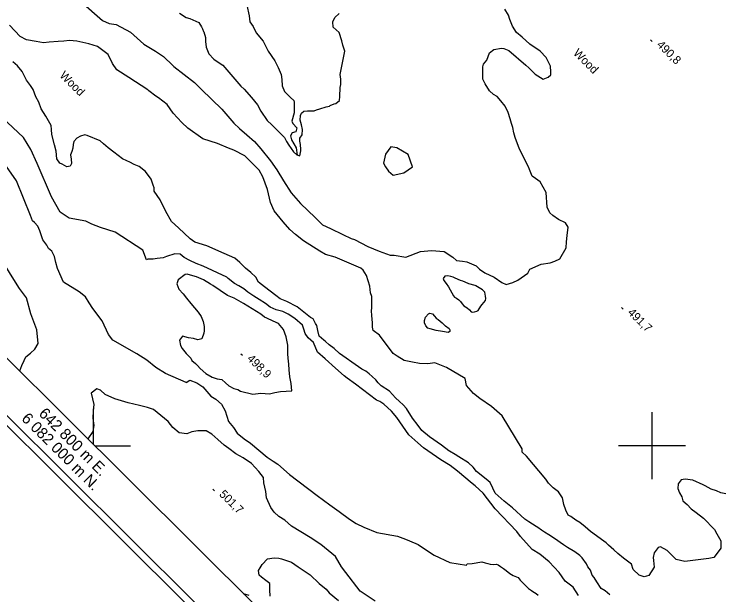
# Model space of a CAD drawing. Extents: x 642515 to 647219, y 6080136 to 6084356.
# Drawn here: x 642771.6 to 643026.5, y 6081946.7 to 6082154.5 of the extents above; entities that cross this region are included whole.
import ezdxf

# ---------------------------------------------------------------- set-up
doc = ezdxf.new("R2010")
doc.units = 0
for name, color, linetype in [('Level 1', 7, 'Continuous'), ('Level 2', 7, 'Continuous'), ('Level 3', 7, 'Continuous'), ('Level 4', 7, 'Continuous'), ('Level 44', 7, 'Continuous'), ('Level 60', 7, 'Continuous'), ('Level 61', 7, 'Continuous')]:
    doc.layers.add(name, color=color, linetype=linetype)

msp = doc.modelspace()

# ---------------------------------------------------------------- linework, layer by layer
at = {"layer": 'Level 1'}
for points in [[(642795.5, 6082159.13), (642803.18, 6082152.26), (642805.67, 6082151.27), (642808.12, 6082150.92), (642813.3, 6082148.12), (642818.08, 6082143.85), (642822.28, 6082141.33), (642825.14, 6082139.38), (642828.41, 6082136.15), (642828.41, 6082136.15), (642828.75, 6082135.85), (642836.19, 6082130.16), (642838.6, 6082127.72), (642842.37, 6082124.07), (642845.97, 6082120.58), (642850.32, 6082115.51), (642852.36, 6082113.7), (642854.92, 6082111.43), (642857.65, 6082109.01), (642859.91, 6082106.4), (642863.4, 6082102.09), (642865.69, 6082098.84), (642868.03, 6082094.94), (642870.87, 6082090.59), (642874.17, 6082086.75), (642879.48, 6082081.74), (642882.06, 6082079.16), (642884.88, 6082077.87), (642889.36, 6082075.72), (642892.36, 6082074.28), (642893.51, 6082073.87), (642898.34, 6082071.41), (642902.31, 6082069.71), (642906.27, 6082068.34), (642907.72, 6082068.26), (642911.96, 6082067.55), (642917.15, 6082069.63), (642921.16, 6082070.03), (642925.7, 6082069.66), (642928.73, 6082067.58), (642930.09, 6082066.37), (642932.2, 6082066.17), (642933.75, 6082065.86), (642937.06, 6082064.45), (642938.34, 6082063.31), (642940.19, 6082061.97), (642943.52, 6082060.39), (642946.37, 6082058.47), (642947.87, 6082057.75), (642950.24, 6082058.54), (642952.04, 6082059.37)], [(642961.08, 6082131.3), (642962.9, 6082131.97), (642963.81, 6082132.83), (642963.83, 6082133.88), (642963.7, 6082135.97), (642962.22, 6082139.11), (642960.07, 6082141.32), (642956.36, 6082143.84), (642953.55, 6082146.33), (642951.59, 6082148.07), (642950.17, 6082150.25), (642949.22, 6082152.61), (642948.71, 6082154.27), (642947.38, 6082156.37)], [(642952.04, 6082059.37), (642955.6, 6082061.84), (642956.31, 6082063.34), (642960.4, 6082065.03), (642963.59, 6082065.55), (642965.33, 6082066.13), (642967.05, 6082067.04), (642969.39, 6082070.89), (642969.5, 6082073.08), (642969.68, 6082075.35), (642970.06, 6082078.36), (642969.08, 6082079.83), (642966.67, 6082081.06), (642964.57, 6082082.46), (642963.46, 6082083.45), (642962.53, 6082085.49), (642962.2, 6082090.79), (642960.04, 6082094.54), (642958.35, 6082095.73), (642957.17, 6082096.62), (642956.22, 6082098.99), (642955.84, 6082099.93), (642952.63, 6082106.27), (642951.09, 6082110.38), (642950.66, 6082112.13), (642950.3, 6082113.96), (642949.81, 6082115.46), (642949.3, 6082117.13), (642948.6, 6082119.42), (642947.49, 6082121.62), (642946.01, 6082123.54), (642944.62, 6082125.08), (642943.29, 6082125.8), (642941.84, 6082127.09), (642940.31, 6082129.66), (642939.49, 6082131.3), (642939.49, 6082132.51), (642939.46, 6082134.37), (642939.45, 6082135.74), (642939.72, 6082136.72), (642940.92, 6082138.08), (642941.89, 6082140.72), (642943.43, 6082141.94), (642946.14, 6082142.42), (642947.03, 6082142.24), (642948.85, 6082141.54), (642954.89, 6082136.33), (642956, 6082135.35), (642958.31, 6082133.15), (642961.08, 6082131.3)], [(642914.29, 6082099.91), (642912.73, 6082104.34), (642908.71, 6082106.68), (642906.59, 6082107.04), (642904.65, 6082104.5), (642903.89, 6082101.23), (642904.61, 6082099.98), (642905.67, 6082098.43), (642907.38, 6082096.92), (642911.19, 6082097.79), (642914.29, 6082099.91)], [(642780.2, 6082036.7), (642779.73, 6082041.54), (642777.62, 6082047.34), (642775.99, 6082053.01), (642773.54, 6082056.39), (642770.89, 6082060.55), (642766.29, 6082067.65), (642766.29, 6082067.65), (642766.29, 6082067.65), (642766.56, 6082068.63), (642765.23, 6082075.14), (642765.02, 6082078.99), (642766.31, 6082081.79), (642766.86, 6082086.48), (642766.85, 6082089.54), (642766.44, 6082091.12), (642765.45, 6082094.44), (642763.59, 6082096.11), (642761.43, 6082097.43), (642759.58, 6082098.78), (642753, 6082104.36)], [(642773.6, 6082026.78), (642773.67, 6082026.94), (642774.28, 6082028.82), (642775.21, 6082030.56), (642775.77, 6082031.87), (642777.45, 6082033.26), (642779.04, 6082034.71), (642780.2, 6082036.7)], [(642900.93, 6081944.47), (642895.6, 6081948), (642890.38, 6081954.73), (642888.82, 6081956.72), (642886.67, 6081960.43), (642881.45, 6081964.76), (642877.61, 6081967.26), (642874.29, 6081969.3), (642870.96, 6081971.34), (642868.59, 6081973.44), (642866.43, 6081974.76), (642864.74, 6081976.26), (642863.52, 6081977.94), (642862.03, 6081981.38), (642861.72, 6081983.76), (642861.06, 6081986.77), (642860.94, 6081988.68), (642859.21, 6081990.82), (642856.63, 6081993.71), (642853.62, 6081995.77), (642850.97, 6081997.21), (642848.45, 6081999.14), (642846.78, 6082000.33), (642844.58, 6082002.28), (642842.38, 6082004.23), (642840.39, 6082005.39), (642837.35, 6082005.37), (642835.29, 6082005.08), (642833.41, 6082004.33), (642830.67, 6082004.65), (642828.47, 6082006.6), (642826.74, 6082008.73), (642821.51, 6082013.07), (642819.39, 6082013.74), (642816.46, 6082014.53), (642812.4, 6082015.4), (642807.67, 6082016.88), (642804.21, 6082018.44), (642802.52, 6082019.94), (642801.21, 6082020.5), (642799.22, 6082018.94), (642800.11, 6082014.83), (642799.93, 6082012.58), (642799.77, 6082010), (642800.09, 6082007.3), (642799.74, 6082005.2), (642797.99, 6082002.54)]]:
    msp.add_lwpolyline(points, dxfattribs=at)
at = {"layer": 'Level 2'}
for points in [[(642830.77, 6082154.98), (642833.22, 6082153.41), (642834.54, 6082153), (642837.71, 6082151.55), (642838.68, 6082150.06), (642839.05, 6082149.27), (642839.43, 6082148.32), (642839.43, 6082148.32), (642839.52, 6082148.24), (642840.13, 6082146.18), (642840.13, 6082144.8), (642840.33, 6082142.79), (642841.37, 6082140.35), (642843.1, 6082138.51), (642845.05, 6082137.1), (642846.31, 6082136.28), (642852.82, 6082128.83), (642854.02, 6082127.77), (642856.63, 6082124.69), (642858.73, 6082122.07), (642859.99, 6082119.88), (642862.22, 6082116.54), (642863.85, 6082114.94), (642866.59, 6082112.36), (642868.4, 6082110.44), (642869.14, 6082109.03), (642870.03, 6082107.63), (642870.83, 6082106.47), (642871.63, 6082105.3), (642872.91, 6082104.17), (642873.89, 6082103.9), (642874.35, 6082105.63), (642874.24, 6082106.18), (642874.22, 6082107.88), (642873.9, 6082109.07), (642873.99, 6082110.21), (642874.73, 6082111.39), (642874.93, 6082113.34), (642874.51, 6082114.93), (642874, 6082116.6)], [(642874, 6082116.6), (642874.14, 6082118.3), (642874.58, 6082119.13), (642875.42, 6082119.91), (642876.7, 6082119.99), (642878.08, 6082119.99), (642879.13, 6082119.97), (642879.91, 6082120.34), (642881.11, 6082120.65), (642883.4, 6082121.36), (642884.6, 6082121.67), (642884.82, 6082121.93), (642886.24, 6082122.5), (642886.8, 6082122.61), (642888.19, 6082123.66), (642888.26, 6082125.12), (642888.39, 6082128.36), (642888.65, 6082129.34), (642888.61, 6082131.36), (642888.35, 6082132.96), (642890.01, 6082141.38), (642889.4, 6082143.45), (642888.98, 6082145.04), (642888.07, 6082147.97), (642885.94, 6082149.87), (642885.73, 6082151.88), (642886.45, 6082153.37), (642887.98, 6082154.76)], [(642899.76, 6082053.52), (642899.2, 6082054.78), (642898.96, 6082057.26), (642897.85, 6082060.98), (642896.68, 6082062.93), (642895.83, 6082063.68), (642886.57, 6082067.64), (642883.13, 6082068.56), (642881.13, 6082069.73), (642875.27, 6082073.41), (642872.39, 6082075.66), (642870.35, 6082077.47), (642867.93, 6082080.22), (642864.78, 6082084.22), (642863.47, 6082087.21), (642862.39, 6082091.82), (642860.66, 6082096.39), (642859.39, 6082098.73), (642854.24, 6082103.9), (642850.25, 6082105.92), (642848.44, 6082106.61), (642844.47, 6082108.31), (642839.22, 6082109.93), (642833.82, 6082113.8), (642831.61, 6082115.76), (642828.51, 6082119.12), (642826.38, 6082122.22), (642823.34, 6082124.62), (642822.34, 6082125.2), (642819.8, 6082127.14), (642819.8, 6082127.14), (642819.46, 6082127.45), (642812.73, 6082131.93), (642808.37, 6082134.6), (642806.79, 6082136.94), (642805.32, 6082140.1), (642801.43, 6082142.96), (642798.3, 6082143.92), (642794.03, 6082144.97), (642791.43, 6082145.15), (642789.34, 6082144.88), (642787.4, 6082144.77), (642784.17, 6082144.59), (642782.08, 6082144.32), (642779.46, 6082144.82), (642776.03, 6082145.44), (642773.7, 6082146.6), (642769.91, 6082150.6)], [(642786.65, 6082105.55), (642786.02, 6082107.76), (642785.05, 6082111.48), (642784.93, 6082113.24), (642784.84, 6082114.68), (642782.93, 6082118.02), (642781.22, 6082120.73), (642780.42, 6082123.09), (642779.4, 6082125.03), (642778.43, 6082127.55), (642777.45, 6082129.01), (642775.95, 6082130.92), (642775.29, 6082132.41), (642774.46, 6082134.05), (642772.79, 6082136.11), (642771.17, 6082137.53)], [(642821.45, 6082066.84), (642819.52, 6082066.89), (642818.97, 6082066.61), (642817.64, 6082070.07), (642807.77, 6082076.55), (642802.53, 6082078.16), (642799.4, 6082079.42), (642797.25, 6082080.42), (642791.24, 6082081.51), (642788.06, 6082083.73), (642785, 6082089.17), (642785, 6082089.17), (642779.81, 6082101.14), (642777.6, 6082106.18), (642774.94, 6082110.38), (642767.28, 6082117.54)], [(642880.91, 6082039.34), (642880.38, 6082041.32), (642880.01, 6082043.14), (642879.57, 6082043.84), (642878.73, 6082045.47), (642877.73, 6082046.05), (642872.98, 6082049.77), (642869.23, 6082051.69), (642866.91, 6082052.67), (642865.39, 6082053.86), (642861.32, 6082056.97), (642859.19, 6082058.69), (642858.19, 6082060.47), (642856.4, 6082062.04), (642854.44, 6082063.61), (642852.46, 6082065.65), (642850.66, 6082067.22), (642846.85, 6082068.91), (642840.64, 6082071.64), (642836.36, 6082072.97), (642834.68, 6082074.15), (642830.47, 6082078.14), (642827.91, 6082080.39), (642825.9, 6082083.96), (642823.85, 6082088.17), (642821.8, 6082091.18), (642821.8, 6082092.38), (642821.41, 6082093.32), (642820.62, 6082095.52), (642818.6, 6082098.21), (642816.39, 6082100), (642814.64, 6082100.77), (642813.06, 6082101.55), (642811.99, 6082102.04), (642810.41, 6082102.83), (642807.28, 6082105.12), (642805.24, 6082106.76), (642803.61, 6082108.18), (642802.42, 6082109.23), (642797.78, 6082111.18), (642796.89, 6082111.36), (642795.3, 6082110.94), (642793.99, 6082110.13), (642793.02, 6082109.02), (642792.77, 6082107.88), (642792.61, 6082106.66), (642792.29, 6082105.43), (642791.73, 6082104.27), (642791.99, 6082102.68), (642792.1, 6082101.07), (642791.6, 6082100.15), (642790.49, 6082099.92), (642788.73, 6082100.85), (642787.9, 6082101.28), (642786.83, 6082102.82), (642786.65, 6082105.55)], [(642787.17, 6082063.57), (642786.56, 6082065.62), (642786.1, 6082067.84), (642785.03, 6082069.7), (642783.84, 6082070.75), (642783.29, 6082071.84), (642781.81, 6082073.76), (642780.81, 6082077.07), (642780.07, 6082078.63), (642778.87, 6082080), (642778.19, 6082080.6), (642777.44, 6082082.49), (642772.4, 6082094.93), (642765.41, 6082104.84)], [(642939.59, 6081983.15), (642936.7, 6081985.7), (642935.68, 6081986.61), (642930.44, 6081990.95), (642927.75, 6081993.04), (642924.41, 6081995.09), (642918.21, 6081999.37), (642916.17, 6082001.18), (642912.95, 6082004.04), (642910.83, 6082007.13), (642908.72, 6082010.21), (642906.81, 6082012.51), (642904.09, 6082014.91), (642902.59, 6082015.95), (642901.44, 6082016.36), (642893.86, 6082022.17), (642890.84, 6082024.24), (642889.82, 6082025.14), (642886.77, 6082027.85), (642883.03, 6082031.16), (642880.32, 6082033.57), (642878.82, 6082037.02), (642876.96, 6082038.67), (642875.9, 6082040.22), (642875.4, 6082041.87), (642874.91, 6082043.21), (642872.11, 6082045.69), (642869.78, 6082047.16), (642867.79, 6082048.16), (642865.42, 6082048.75), (642863.28, 6082049.74), (642861.67, 6082051.01), (642859.42, 6082052.4), (642857.5, 6082053.65), (642855.25, 6082055.04), (642853.89, 6082056.25), (642852.13, 6082057.35), (642850.56, 6082058.14), (642848.28, 6082060.01), (642847.77, 6082060.46), (642839.26, 6082064.37), (642836.79, 6082065.35), (642834.56, 6082066.42), (642832.49, 6082067.5), (642831.05, 6082068.62), (642829.12, 6082068.83), (642826.21, 6082067.77), (642824.95, 6082067.37), (642822.79, 6082067.16), (642821.45, 6082066.84)], [(642833.27, 6082022.7), (642825.86, 6082025.94), (642822.36, 6082028.14), (642819.16, 6082030.67), (642815.49, 6082033.02), (642806.93, 6082037.88), (642805.37, 6082039.88), (642803.06, 6082044.79), (642799.75, 6082049.24), (642798.5, 6082051.26), (642797.17, 6082053.34), (642794.89, 6082055.21), (642789.31, 6082058.65), (642787.17, 6082063.57)], [(642938.81, 6082050.02), (642939.25, 6082050.69), (642940.46, 6082052.05), (642940.53, 6082052.82), (642940.52, 6082053.66), (642940.19, 6082055.01), (642939.33, 6082055.93), (642938.16, 6082056.58), (642937.04, 6082057.28), (642936.7, 6082057.42), (642934.49, 6082058.09), (642933.13, 6082058.62), (642932.3, 6082058.97), (642931.56, 6082059.25), (642930.69, 6082059.64), (642929.37, 6082060.21), (642928.92, 6082060.38), (642928.02, 6082060.65), (642927, 6082060.87), (642925.95, 6082060.81), (642925.28, 6082059.96), (642925.53, 6082059.21), (642926.31, 6082058.21), (642927.23, 6082057.02), (642929, 6082053.78), (642929.39, 6082053.28), (642930.1, 6082052.96), (642930.86, 6082052.28), (642931.5, 6082051.71), (642932.07, 6082050.9), (642932.72, 6082050.17), (642933.31, 6082049.81), (642933.89, 6082049.44), (642934.7, 6082048.72), (642935.27, 6082048.07), (642935.84, 6082047.86), (642936.48, 6082047.98), (642937.31, 6082048.23), (642937.89, 6082048.55), (642938.81, 6082050.02)], [(643000.55, 6081960.06), (643000.69, 6081959.02), (643000.84, 6081956.61), (642999.01, 6081953.68), (642997.35, 6081953.18), (642995.46, 6081953.79), (642993.41, 6081955.76), (642992.81, 6081957.66), (642989.86, 6081959.82), (642987.9, 6081961.55), (642986.46, 6081962.83), (642984.58, 6081964.5), (642983.65, 6081965.33), (642982.81, 6081965.92), (642978.09, 6081969.34), (642976.13, 6081971.08), (642974.27, 6081972.58), (642972.77, 6081973.45), (642971.07, 6081974.8), (642970.08, 6081975.23), (642969.25, 6081977.03), (642968.48, 6081979.08), (642968.09, 6081981.39), (642966.59, 6081983.64), (642964.65, 6081985.05), (642963.02, 6081986.65), (642962.05, 6081988.12), (642955.1, 6081996.41), (642953.57, 6081997.76), (642953.57, 6081998.97), (642946.41, 6082010.79), (642942.58, 6082014.19), (642938.38, 6082017), (642936.18, 6082018.8), (642933.67, 6082021.63), (642933.12, 6082024.1), (642926.43, 6082028.05), (642922.31, 6082029.73), (642919.75, 6082029.42), (642916.84, 6082029.57), (642914.32, 6082029.98), (642911.38, 6082030.61), (642908.79, 6082032.15), (642907.37, 6082033.11), (642902.54, 6082039.67), (642900.26, 6082041.39), (642899.94, 6082042.58), (642900.01, 6082044.03), (642899.69, 6082046.75), (642899.59, 6082048.36), (642899.68, 6082049.49), (642899.76, 6082053.52)], [(642922.8, 6082041.36), (642920.63, 6082041.92), (642919.85, 6082042.23), (642919.08, 6082042.99), (642918.61, 6082044.09), (642918.56, 6082044.9), (642919.01, 6082046.09), (642919.98, 6082047.36), (642920.53, 6082047.55), (642921.43, 6082047.36), (642922.13, 6082046.44), (642922.81, 6082045.76), (642923.48, 6082045.31), (642924.89, 6082044.07), (642925.91, 6082043.16), (642926.12, 6082042.97), (642927.46, 6082042.09), (642927.74, 6082041.54), (642927.65, 6082041.01), (642927.11, 6082040.57), (642925.04, 6082040.97), (642922.8, 6082041.36)], [(642977.08, 6081956.74), (642976.61, 6081957.76), (642975.09, 6081959.99), (642974.24, 6081960.74), (642972.46, 6081962.15), (642969.86, 6081963.67), (642968.43, 6081964.63), (642965.15, 6081966.91), (642963.13, 6081968.22), (642961.62, 6081969.09), (642960.52, 6081969.9), (642959.25, 6081970.87), (642958.67, 6081971.23), (642955.99, 6081972.82), (642954.56, 6081973.78), (642950.11, 6081977.83), (642947.13, 6081980.29), (642943.88, 6081983.14), (642943.12, 6081984.86), (642942.1, 6081986.96), (642940.73, 6081988.16), (642937.18, 6081990.83), (642936.03, 6081992.44), (642934.32, 6081993.94), (642930.95, 6081996.13), (642929.54, 6081996.93), (642927.6, 6081998.17), (642927.27, 6081998.31), (642924.65, 6082000.31), (642920.34, 6082003.33), (642917.71, 6082005.49), (642916.3, 6082007.33), (642914.35, 6082009.94), (642912.11, 6082013.41), (642910.98, 6082014.71), (642909.61, 6082015.9), (642908.16, 6082017.18), (642906.07, 6082019.62), (642903.13, 6082021.52), (642902.01, 6082022.65), (642901.13, 6082023.72), (642899.81, 6082024.88), (642898.74, 6082025.82), (642897.59, 6082026.75), (642896.17, 6082027.54), (642894.99, 6082028.35), (642888.16, 6082033.13), (642886.2, 6082034.86), (642884.5, 6082036.19), (642883.13, 6082037.39), (642882.53, 6082037.92), (642880.91, 6082039.34)], [(642833.27, 6082022.7), (642834.53, 6082023.5), (642837.07, 6082022.62), (642839.17, 6082021.23), (642842.04, 6082017.81), (642843.8, 6082016.72), (642845.84, 6082014.93), (642847.2, 6082012.53), (642848.42, 6082008.76), (642850.16, 6082006.62), (642851.5, 6082004.55), (642853.96, 6082002.54), (642856.23, 6082001), (642859.29, 6081998.47), (642862.26, 6081996.02), (642864.44, 6081994.56), (642866.03, 6081993.46), (642870.29, 6081989.73), (642880.17, 6081982.27), (642884.64, 6081978.95), (642888, 6081976.6), (642891.72, 6081973.8), (642894.14, 6081972.27), (642896.88, 6081970.93), (642901.57, 6081969.07), (642908.96, 6081967.71), (642911.76, 6081966.61), (642913.24, 6081966.06), (642916.29, 6081964.74), (642919.31, 6081962.69), (642922.08, 6081960.86), (642927.7, 6081958.34), (642933.66, 6081957.33), (642933.95, 6081957.75), (642935.74, 6081957.91), (642939.18, 6081958.58), (642940.33, 6081958.17), (642941.35, 6081957.88), (642942.17, 6081957.69), (642943.17, 6081957.63), (642944.41, 6081957.67), (642945.03, 6081957.43), (642945.83, 6081956.81), (642946.88, 6081956.11), (642947.89, 6081955.46), (642949.16, 6081954.34), (642950.37, 6081953.65), (642952.22, 6081952.93), (642952.93, 6081952.02), (642954.27, 6081950.54)], [(643026.59, 6081982.81), (643024.79, 6081983.19), (643023.22, 6081983.98), (643021.33, 6081984.59), (643019.16, 6081985.75), (643018.42, 6081986.11), (643014.7, 6081987.74), (643012.02, 6081988.14), (643010.58, 6081987.89), (643009.47, 6081986.46), (643009.33, 6081984.76), (643009.91, 6081983.18), (643010.8, 6081981.78), (643011.21, 6081980.36), (643012.74, 6081979), (643014.12, 6081977.47), (643015.98, 6081976.13), (643018.59, 6081974.11), (643022.46, 6081970.08), (643023.36, 6081968.52), (643024.72, 6081966.1), (643024.8, 6081963.45), (643022.8, 6081960.67), (643022.27, 6081960.07), (643020.44, 6081959.72), (643011.9, 6081958.64), (643008.8, 6081959.42), (643007.18, 6081960.86), (643005.54, 6081962.61), (643003.21, 6081963.92), (643002.34, 6081963.63), (643000.85, 6081961.77), (643000.55, 6081960.06)], [(642973.77, 6081946.48), (642971.83, 6081949.42), (642968.96, 6081951.65), (642966.84, 6081954.74), (642963.24, 6081958.54), (642959.87, 6081961.23), (642957.19, 6081963), (642953.06, 6081967.57), (642951.66, 6081969.41), (642943.95, 6081977.46), (642939.59, 6081983.15)], [(642863.29, 6081946.25), (642863.21, 6081948.56), (642863.15, 6081950.72), (642861.72, 6081951.82), (642860.2, 6081953), (642859.35, 6081953.75), (642859.16, 6081955.42), (642859.73, 6081956.41), (642860.45, 6081957.58), (642862.32, 6081959.54), (642864.77, 6081959.94), (642866.46, 6081959.81), (642867.35, 6081959.63), (642870.95, 6081958.43), (642873.38, 6081956.75), (642877.64, 6081953.91), (642880.89, 6081950.76), (642883.43, 6081948.69), (642884.47, 6081947.48), (642887.85, 6081944.66)], [(642985.06, 6081946.72), (642983.28, 6081948.14), (642981.94, 6081949.01), (642980.34, 6081951.32), (642979.43, 6081952.87), (642978.72, 6081953.79), (642978.04, 6081955.6), (642977.08, 6081956.74)], [(642954.27, 6081950.54), (642955.89, 6081948.96), (642956.99, 6081948.23), (642957.45, 6081947.9), (642958.66, 6081947.14), (642959.3, 6081946.58)], [(642853.66, 6081947.2), (642855.67, 6081946.63)]]:
    msp.add_lwpolyline(points, dxfattribs=at)
msp.add_lwpolyline([(642859.91, 6082018.87), (642863.05, 6082018.66), (642864.95, 6082019.09), (642867, 6082019.53), (642871.08, 6082019.7), (642870.84, 6082022.33), (642870.37, 6082024.71), (642870.06, 6082027.26), (642870.01, 6082029.26), (642869.72, 6082031.49), (642869.7, 6082033.01), (642869.59, 6082036.13), (642869.01, 6082039.06), (642868.13, 6082041.66), (642866.24, 6082043.79), (642864.34, 6082044.72), (642862.11, 6082045.79), (642861.29, 6082046.06), (642860.02, 6082047.19), (642853.7, 6082050.98), (642850.45, 6082052.95), (642848.07, 6082053.85), (642842.8, 6082057.46), (642841.97, 6082057.9), (642839.47, 6082059.51), (642836.92, 6082060.56), (642834.72, 6082061.15), (642833.57, 6082061.56), (642832.86, 6082061.44), (642830.34, 6082059.45), (642829.86, 6082058.05), (642830.54, 6082056.09), (642832.16, 6082054.5), (642833.38, 6082052.97), (642834.86, 6082051.05), (642837.53, 6082047.93), (642838.59, 6082046.39), (642839.35, 6082044.51), (642839.61, 6082042.76), (642839.63, 6082041.23), (642839.52, 6082040.43), (642838.84, 6082038.3), (642837.42, 6082038.05), (642835.79, 6082038.44), (642834.09, 6082038.74), (642831.89, 6082039.33), (642830.86, 6082037.82), (642831.21, 6082036), (642831.76, 6082034.91), (642833.23, 6082033.15), (642834.86, 6082031.41), (642835.23, 6082030.63), (642836.5, 6082029.5), (642837.26, 6082028.82), (642838.29, 6082027.76), (642840.32, 6082025.96), (642842.48, 6082024.64), (642844.37, 6082024.03), (642845.98, 6082023.81), (642847.34, 6082022.61), (642848.52, 6082021.56), (642850.35, 6082020.54), (642851.73, 6082020.22), (642852.73, 6082019.64), (642857.05, 6082018.54)], close=True, dxfattribs=at)
at = {"layer": 'Level 3'}
for p, q in [((642999.57, 6082145.4), (643000.15, 6082144.84)), ((642989.16, 6082049.56), (642989.73, 6082049)), ((642852.78, 6082033.04), (642853.35, 6082032.48)), ((642842.81, 6081984.51), (642843.38, 6081983.95))]:
    msp.add_line(p, q, dxfattribs=at)
at = {"layer": 'Level 4'}
msp.add_lwpolyline([(642854.97, 6082157.81), (642855.81, 6082153.96), (642855.98, 6082151.83), (642857.17, 6082150.17), (642858.31, 6082147.94), (642860.84, 6082144.87), (642862.54, 6082141.39), (642864.93, 6082137.82), (642866.12, 6082135.48), (642867.29, 6082132.93), (642867.55, 6082131.17), (642867.61, 6082128.92), (642868.5, 6082126.92), (642870.56, 6082124.78), (642871.84, 6082123.73), (642871.95, 6082123.1), (642871.86, 6082119.22), (642871.03, 6082116.31), (642871.45, 6082115.41), (642872.87, 6082113.93), (642872.51, 6082112.5), (642871.16, 6082112.09), (642870.54, 6082111.05), (642870.95, 6082109.55), (642872.61, 6082106.71), (642873.01, 6082104.07)], dxfattribs=at)
at = {"layer": 'Level 60'}
for p, q in [((642800, 6082000.54), (642800, 6082013.31)), ((642800.46, 6082000), (642813.31, 6082000))]:
    msp.add_line(p, q, dxfattribs=at)
for points in [[(643756.15, 6083509.1), (645893.11, 6081385.05), (644652.25, 6080135.58), (642514.75, 6082260.08)], [(642518.29, 6082260.09), (643756.16, 6083505.56), (645889.57, 6081385.04), (644651.74, 6080139.63)], [(643756.23, 6083485.06), (645517.55, 6081734.46), (644300.6, 6080509.08), (642538.79, 6082260.16)]]:
    msp.add_lwpolyline(points, close=True, dxfattribs=at)
at = {"layer": 'Level 61'}
for p, q in [((643000, 6082012.16), (643000, 6081988.16)), ((643012.16, 6082000), (642988.16, 6082000))]:
    msp.add_line(p, q, dxfattribs=at)

# ---------------------------------------------------------------- texts
at = {"layer": 'Level 3'}
for s, p in [('490,8', (643001.6, 6082143.36)), ('491,7', (642991.18, 6082047.51)), ('498,9', (642854.81, 6082031)), ('501,7', (642844.84, 6081982.46))]:
    msp.add_text(s, height=3, rotation=315.59, dxfattribs=at).set_placement(p)
at = {"layer": 'Level 44'}
for p in [(642971.69, 6082140.4), (642787.66, 6082132.4)]:
    msp.add_text('Wood', height=3, rotation=315.1749, dxfattribs=at).set_placement(p)
at = {"layer": 'Level 61'}
for s, p in [('642 800 m E.', (642780.14, 6082011.27)), ('6 082 000 m N.', (642773.96, 6082009.5))]:
    msp.add_text(s, height=4, rotation=315.175, dxfattribs=at).set_placement(p)

doc.saveas('drawing.dxf')
